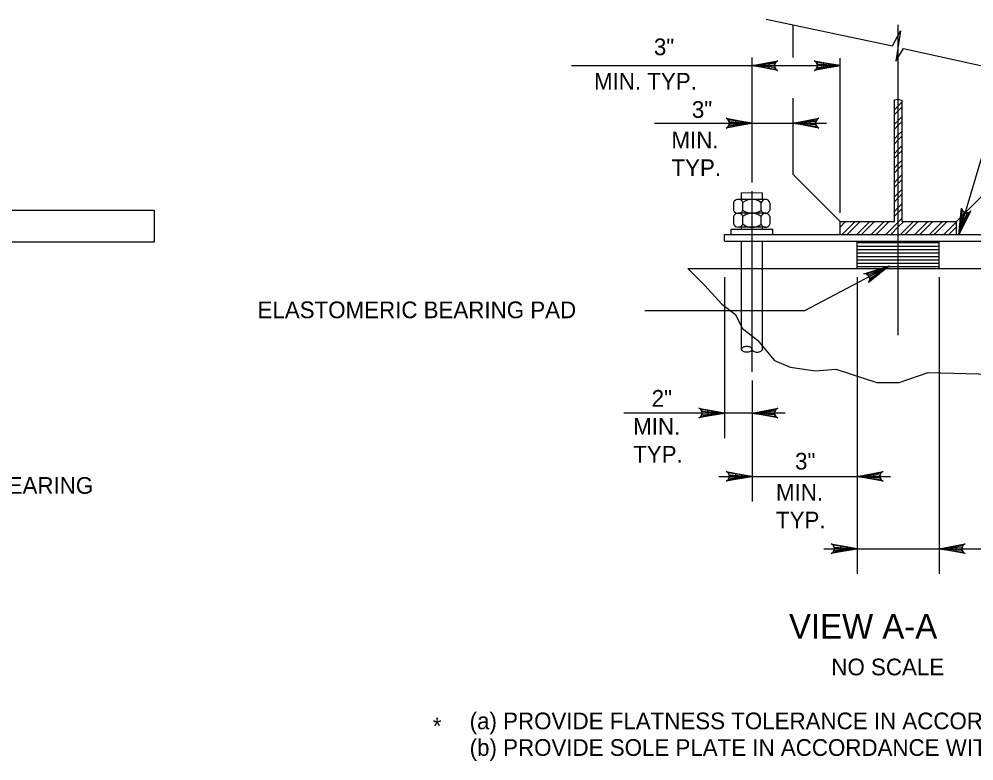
# Model space of a CAD drawing. Extents: x 638175 to 640495, y 294277 to 298435.
# Drawn here: x 639510.9 to 639682.6, y 298033.7 to 298167 of the extents above; entities that cross this region are included whole.
import ezdxf

# ---------------------------------------------------------------- set-up
doc = ezdxf.new("R2010")
doc.units = 0
for name, color, linetype in [('3', 7, 'Continuous'), ('4', 7, 'Continuous'), ('8', 7, 'Continuous')]:
    doc.layers.add(name, color=color, linetype=linetype)

msp = doc.modelspace()

# ---------------------------------------------------------------- linework, layer by layer
at = {"layer": '3'}
for p, q in [((639650.07, 298160.09), (639650.07, 298165.95)), ((639668.98, 298110.18), (639668.98, 298165.93)), ((639650.07, 298139.06), (639650.07, 298152.76)), ((639668.28, 298152.42), (639668.34, 298152.48)), ((639668.28, 298130.61), (639668.28, 298152.47)), ((639668.98, 298151.38), (639669.68, 298152.08)), ((639669.68, 298130.61), (639669.68, 298152.35)), ((639668.28, 298150.68), (639668.98, 298151.38)), ((639668.28, 298149.81), (639668.98, 298150.51)), ((639668.98, 298150.51), (639669.68, 298151.21)), ((639668.28, 298148.07), (639668.98, 298148.77)), ((639668.98, 298148.77), (639669.68, 298149.47)), ((639668.98, 298147.9), (639669.68, 298148.6)), ((639668.28, 298147.2), (639668.98, 298147.9)), ((639668.28, 298145.46), (639668.98, 298146.16)), ((639668.28, 298144.59), (639668.98, 298145.29)), ((639668.98, 298146.16), (639669.68, 298146.86)), ((639668.98, 298145.29), (639669.68, 298145.99)), ((639668.28, 298142.85), (639668.98, 298143.55)), ((639668.98, 298143.55), (639669.68, 298144.25)), ((639668.28, 298141.98), (639668.98, 298142.68)), ((639668.98, 298142.68), (639669.68, 298143.38)), ((639668.28, 298140.24), (639668.98, 298140.94)), ((639668.28, 298139.37), (639668.98, 298140.07)), ((639668.98, 298140.94), (639669.68, 298141.64)), ((639668.98, 298140.07), (639669.68, 298140.77)), ((639668.28, 298137.63), (639668.98, 298138.33)), ((639668.98, 298138.33), (639669.68, 298139.03)), ((639668.28, 298136.76), (639668.98, 298137.46)), ((639668.98, 298137.46), (639669.68, 298138.16)), ((639644.56, 298135.72), (639640.81, 298135.73)), ((639640.81, 298134.57), (639640.81, 298135.73)), ((639642.69, 298103.61), (639642.69, 298136.04)), ((639644.56, 298134.57), (639644.56, 298135.72)), ((639668.28, 298135.02), (639668.98, 298135.72)), ((639668.28, 298134.15), (639668.98, 298134.85)), ((639668.98, 298135.72), (639669.68, 298136.42)), ((639668.98, 298134.85), (639669.68, 298135.55)), ((639639.35, 298134), (639639.35, 298132.66)), ((639645.15, 298134.57), (639640.17, 298134.58)), ((639641.05, 298132.65), (639641.05, 298134)), ((639644.33, 298132.65), (639644.33, 298133.99)), ((639645.91, 298133.98), (639645.91, 298132.64)), ((639668.98, 298133.11), (639669.68, 298133.81)), ((639639.35, 298131.5), (639639.34, 298130.16)), ((639645.15, 298132.07), (639640.17, 298132.08)), ((639641.04, 298130.15), (639641.04, 298131.49)), ((639644.32, 298130.15), (639644.33, 298131.49)), ((639645.91, 298131.48), (639645.91, 298130.14)), ((639668.28, 298132.41), (639668.98, 298133.11)), ((639668.28, 298131.54), (639668.98, 298132.24)), ((639668.98, 298132.24), (639669.68, 298132.94)), ((639658.51, 298128.27), (639658.51, 298130.61)), ((639658.51, 298130.61), (639668.28, 298130.61)), ((639658.51, 298130.47), (639658.65, 298130.61)), ((639658.51, 298129.6), (639659.52, 298130.61)), ((639658.92, 298128.27), (639661.26, 298130.61)), ((639659.79, 298128.27), (639662.13, 298130.61)), ((639661.53, 298128.27), (639663.87, 298130.61)), ((639662.4, 298128.27), (639664.74, 298130.61)), ((639664.14, 298128.27), (639666.48, 298130.61)), ((639665.01, 298128.27), (639667.35, 298130.61)), ((639666.75, 298128.27), (639668.98, 298130.5)), ((639668.98, 298130.5), (639669.68, 298131.2)), ((639668.98, 298129.63), (639669.96, 298130.61)), ((639669.36, 298128.27), (639671.7, 298130.61)), ((639669.68, 298130.61), (639679.45, 298130.61)), ((639670.23, 298128.27), (639672.57, 298130.61)), ((639671.97, 298128.27), (639674.31, 298130.61)), ((639672.84, 298128.27), (639675.18, 298130.61)), ((639674.58, 298128.27), (639676.92, 298130.61)), ((639675.45, 298128.27), (639677.79, 298130.61)), ((639677.19, 298128.27), (639679.45, 298130.53)), ((639679.45, 298128.27), (639679.45, 298130.61)), ((639637.77, 298128.27), (639700.2, 298128.27)), ((639637.77, 298127.09), (639637.77, 298128.27)), ((639638.95, 298129.25), (639646.43, 298129.25)), ((639638.95, 298128.27), (639638.95, 298129.25)), ((639645.14, 298129.57), (639640.16, 298129.58)), ((639640.81, 298129.25), (639640.81, 298129.57)), ((639644.56, 298129.25), (639644.56, 298129.57)), ((639646.43, 298128.27), (639646.43, 298129.25)), ((639667.62, 298128.27), (639668.98, 298129.63)), ((639678.06, 298128.27), (639679.45, 298129.66)), ((639637.77, 298127.09), (639700.2, 298127.09)), ((639640.81, 298122.17), (639640.81, 298127.09)), ((639644.56, 298122.17), (639644.56, 298127.09)), ((639661.6, 298122.17), (639661.6, 298127.09)), ((639661.6, 298127.09), (639661.6, 298127.09)), ((639661.6, 298126.81), (639668.98, 298126.81)), ((639668.98, 298126.81), (639676.36, 298126.81)), ((639676.36, 298122.17), (639676.36, 298127.09)), ((639661.6, 298126.19), (639668.98, 298126.19)), ((639661.6, 298125.57), (639668.98, 298125.57)), ((639661.6, 298124.96), (639668.98, 298124.96)), ((639668.98, 298126.19), (639676.36, 298126.19)), ((639668.98, 298125.57), (639676.36, 298125.57)), ((639668.98, 298124.96), (639676.36, 298124.96)), ((639661.6, 298124.34), (639668.98, 298124.34)), ((639661.6, 298123.73), (639668.98, 298123.73)), ((639661.6, 298123.11), (639668.98, 298123.11)), ((639668.98, 298124.34), (639676.36, 298124.34)), ((639668.98, 298123.73), (639676.36, 298123.73)), ((639668.98, 298123.11), (639676.36, 298123.11)), ((639631.13, 298122.17), (639703.15, 298122.17)), ((639640.81, 298107.62), (639640.81, 298122.17)), ((639644.59, 298122.17), (639644.56, 298122.2)), ((639644.56, 298107.62), (639644.56, 298122.17)), ((639661.6, 298122.5), (639668.98, 298122.5)), ((639668.98, 298122.5), (639676.36, 298122.5))]:
    msp.add_line(p, q, dxfattribs=at)
for points in [[(639668.28, 298152.47), (639668.92, 298152.59), (639669.68, 298152.35)], [(639631.13, 298122.17), (639634.2, 298119.1), (639637.26, 298115.73), (639639.72, 298113.89), (639640.94, 298111.44), (639643.7, 298109.3), (639646.76, 298105.63), (639649.52, 298104.4), (639654.12, 298103.79), (639657.79, 298104.09), (639665.15, 298101.64), (639669.13, 298101.64), (639674.34, 298103.48), (639685.68, 298103.17), (639688.44, 298103.79), (639689.67, 298107.16), (639691.2, 298112.98), (639694.87, 298116.96), (639699.17, 298118.8), (639703.15, 298122.17)]]:
    msp.add_lwpolyline(points, dxfattribs=at)
for centre, radius, start, end in [((639640.2, 298133.67), 0.912, 88.0545, 158.5946), ((639640.2, 298133.67), 0.912, 21.1685, 88.0545), ((639642.69, 298131.96), 2.61, 50.9315, 128.8315), ((639645.12, 298133.74), 0.829, 17.3333, 162.4297), ((639640.2, 298132.99), 0.912, 201.1685, 271.7086), ((639640.19, 298131.16), 0.912, 88.0545, 158.5946), ((639640.2, 298132.99), 0.912, 271.7086, 338.5946), ((639640.19, 298131.16), 0.912, 21.1685, 88.0545), ((639642.68, 298129.46), 2.61, 50.9315, 128.8315), ((639642.69, 298134.68), 2.61, 230.9315, 308.8315), ((639645.12, 298132.89), 0.829, 197.3333, 342.4297), ((639645.12, 298131.24), 0.829, 17.3333, 162.4297), ((639640.19, 298130.49), 0.912, 201.1685, 271.7086), ((639640.19, 298130.49), 0.912, 271.7086, 338.5946), ((639642.69, 298132.18), 2.61, 230.9315, 308.8315), ((639645.11, 298130.39), 0.829, 197.3333, 342.4297), ((639641.09, 298107.64), 0.278, 142.0693, 180), ((639641.09, 298107.64), 0.278, 180, 217.9307), ((639641.41, 298107.4), 0.674, 117.9903, 142.0693), ((639641.41, 298107.89), 0.674, 217.9307, 242.0097), ((639641.61, 298107.01), 1.12, 102.4157, 117.9903), ((639641.75, 298106.39), 1.75, 90, 102.4157), ((639641.75, 298106.39), 1.75, 77.5843, 90), ((639641.89, 298107.01), 1.12, 62.0097, 77.5843), ((639642.1, 298107.4), 0.674, 37.9307, 62.0097), ((639642.1, 298107.89), 0.674, 297.9903, 322.0693), ((639642.41, 298107.64), 0.278, 0, 37.9307), ((639642.41, 298107.64), 0.278, 322.0693, 0), ((639642.96, 298107.62), 0.278, 180, 217.9307), ((639643.28, 298107.87), 0.674, 217.9307, 242.0097), ((639643.97, 298107.87), 0.674, 297.9903, 322.0693), ((639644.28, 298107.62), 0.278, 322.0693, 360), ((639644.28, 298107.62), 0.278, 360, 1.757), ((639641.61, 298108.28), 1.12, 242.0097, 257.5843), ((639641.75, 298108.9), 1.75, 257.5843, 270), ((639641.75, 298108.9), 1.75, 270, 282.4157), ((639641.89, 298108.28), 1.12, 282.4157, 297.9903), ((639643.48, 298108.26), 1.12, 242.0097, 257.5843), ((639643.62, 298108.88), 1.75, 257.5843, 270), ((639643.62, 298108.88), 1.75, 270, 282.4157), ((639643.76, 298108.26), 1.12, 282.4157, 297.9903)]:
    msp.add_arc(centre, radius, start, end, dxfattribs=at)
at = {"layer": '4'}
for p, q in [((639645.23, 298166.98), (639667.92, 298162.15)), ((639667.92, 298162.15), (639669.41, 298164.9)), ((639669.41, 298164.9), (639668.55, 298159.44)), ((639668.55, 298159.44), (639669.92, 298161.71)), ((639669.92, 298161.71), (639695.22, 298156.13)), ((639642.69, 298137.61), (639642.69, 298160.06)), ((639658.51, 298132.17), (639658.51, 298159.94)), ((639610.21, 298158.61), (639658.51, 298158.61)), ((639679.89, 298128.27), (639686.9, 298151.98)), ((639625.17, 298148.28), (639656.07, 298148.28)), ((639493.67, 298132.65), (639535.19, 298132.65)), ((639535.19, 298132.65), (639535.19, 298126.88)), ((639535.19, 298126.88), (639493.67, 298126.88)), ((639667.35, 298122.57), (639652.14, 298114.57)), ((639637.77, 298120.6), (639637.77, 298091.68)), ((639661.6, 298120.6), (639661.6, 298067.29)), ((639676.36, 298120.6), (639676.36, 298067.29)), ((639652.14, 298114.57), (639623.39, 298114.57)), ((639642.69, 298102.04), (639642.69, 298080.28)), ((639648.66, 298096.18), (639619.67, 298096.18)), ((639636.72, 298084.78), (639667.6, 298084.78)), ((639655.63, 298071.79), (639764.22, 298071.79))]:
    msp.add_line(p, q, dxfattribs=at)
for points in [[(639642.69, 298158.61), (639647.35, 298159.48), (639646.99, 298159.23), (639646.8, 298158.92), (639646.75, 298158.61), (639646.8, 298158.3), (639646.99, 298157.98), (639647.35, 298157.73), (639642.69, 298158.61), (639646.99, 298157.98), (639646.8, 298158.3), (639642.69, 298158.61), (639646.75, 298158.61), (639646.8, 298158.92), (639642.69, 298158.61), (639646.99, 298159.23)], [(639658.51, 298158.61), (639653.85, 298157.73), (639654.21, 298157.98), (639654.39, 298158.3), (639654.45, 298158.61), (639654.39, 298158.92), (639654.21, 298159.23), (639653.85, 298159.48), (639658.51, 298158.61), (639654.21, 298159.23), (639654.39, 298158.92), (639658.51, 298158.61), (639654.45, 298158.61), (639654.39, 298158.3), (639658.51, 298158.61), (639654.21, 298157.98)], [(639642.69, 298148.28), (639638.03, 298147.4), (639638.38, 298147.65), (639638.57, 298147.96), (639638.62, 298148.28), (639638.57, 298148.59), (639638.38, 298148.9), (639638.03, 298149.15), (639642.69, 298148.28), (639638.38, 298148.9), (639638.57, 298148.59), (639642.69, 298148.28), (639638.62, 298148.28), (639638.57, 298147.96), (639642.69, 298148.28), (639638.38, 298147.65)], [(639650.07, 298148.28), (639654.73, 298149.15), (639654.37, 298148.9), (639654.19, 298148.59), (639654.13, 298148.28), (639654.19, 298147.96), (639654.37, 298147.65), (639654.73, 298147.4), (639650.07, 298148.28), (639654.37, 298147.65), (639654.19, 298147.96), (639650.07, 298148.28), (639654.13, 298148.28), (639654.19, 298148.59), (639650.07, 298148.28), (639654.37, 298148.9)], [(639679.89, 298128.27), (639680.38, 298132.99), (639680.51, 298132.57), (639680.76, 298132.31), (639681.04, 298132.17), (639681.36, 298132.13), (639681.71, 298132.22), (639682.05, 298132.49), (639679.89, 298128.27), (639681.71, 298132.22), (639681.36, 298132.13), (639679.89, 298128.27), (639681.04, 298132.17), (639680.76, 298132.31), (639679.89, 298128.27), (639680.51, 298132.57)], [(639667.35, 298122.57), (639663.63, 298119.62), (639663.83, 298120.01), (639663.85, 298120.37), (639663.75, 298120.67), (639663.56, 298120.93), (639663.25, 298121.12), (639662.82, 298121.17), (639667.35, 298122.57), (639663.25, 298121.12), (639663.56, 298120.93), (639667.35, 298122.57), (639663.75, 298120.67), (639663.85, 298120.37), (639667.35, 298122.57), (639663.83, 298120.01)], [(639637.77, 298096.18), (639633.11, 298095.31), (639633.46, 298095.56), (639633.65, 298095.87), (639633.7, 298096.18), (639633.65, 298096.49), (639633.46, 298096.81), (639633.11, 298097.06), (639637.77, 298096.18), (639633.46, 298096.81), (639633.65, 298096.49), (639637.77, 298096.18), (639633.7, 298096.18), (639633.65, 298095.87), (639637.77, 298096.18), (639633.46, 298095.56)], [(639642.69, 298096.18), (639647.35, 298097.06), (639646.99, 298096.81), (639646.8, 298096.49), (639646.75, 298096.18), (639646.8, 298095.87), (639646.99, 298095.56), (639647.35, 298095.31), (639642.69, 298096.18), (639646.99, 298095.56), (639646.8, 298095.87), (639642.69, 298096.18), (639646.75, 298096.18), (639646.8, 298096.49), (639642.69, 298096.18), (639646.99, 298096.81)], [(639642.69, 298084.78), (639638.03, 298083.91), (639638.38, 298084.15), (639638.57, 298084.47), (639638.62, 298084.78), (639638.57, 298085.09), (639638.38, 298085.4), (639638.03, 298085.65), (639642.69, 298084.78), (639638.38, 298085.4), (639638.57, 298085.09), (639642.69, 298084.78), (639638.62, 298084.78), (639638.57, 298084.47), (639642.69, 298084.78), (639638.38, 298084.15)], [(639661.6, 298084.78), (639666.26, 298085.65), (639665.9, 298085.4), (639665.72, 298085.09), (639665.66, 298084.78), (639665.72, 298084.47), (639665.9, 298084.15), (639666.26, 298083.91), (639661.6, 298084.78), (639665.9, 298084.15), (639665.72, 298084.47), (639661.6, 298084.78), (639665.66, 298084.78), (639665.72, 298085.09), (639661.6, 298084.78), (639665.9, 298085.4)], [(639661.6, 298071.79), (639656.94, 298070.92), (639657.3, 298071.17), (639657.48, 298071.48), (639657.54, 298071.79), (639657.48, 298072.1), (639657.3, 298072.42), (639656.94, 298072.66), (639661.6, 298071.79), (639657.3, 298072.42), (639657.48, 298072.1), (639661.6, 298071.79), (639657.54, 298071.79), (639657.48, 298071.48), (639661.6, 298071.79), (639657.3, 298071.17)], [(639676.36, 298071.79), (639681.02, 298072.66), (639680.66, 298072.42), (639680.48, 298072.1), (639680.42, 298071.79), (639680.48, 298071.48), (639680.66, 298071.17), (639681.02, 298070.92), (639676.36, 298071.79), (639680.66, 298071.17), (639680.48, 298071.48), (639676.36, 298071.79), (639680.42, 298071.79), (639680.48, 298072.1), (639676.36, 298071.79), (639680.66, 298072.42)]]:
    msp.add_lwpolyline(points, dxfattribs=at)
for points in [[(639645.69, 298159.11), (639645.69, 298158.11), (639642.69, 298158.61)], [(639655.51, 298159.11), (639655.51, 298158.11), (639658.51, 298158.61)], [(639639.69, 298148.78), (639639.69, 298147.78), (639642.69, 298148.28)], [(639653.07, 298148.78), (639653.07, 298147.78), (639650.07, 298148.28)], [(639681.23, 298131.02), (639680.27, 298131.32), (639679.83, 298128.32)], [(639634.77, 298096.68), (639634.77, 298095.68), (639637.77, 298096.18)], [(639645.69, 298096.68), (639645.69, 298095.68), (639642.69, 298096.18)], [(639639.69, 298085.28), (639639.69, 298084.28), (639642.69, 298084.78)], [(639664.6, 298085.28), (639664.6, 298084.28), (639661.6, 298084.78)], [(639658.6, 298072.29), (639658.6, 298071.29), (639661.6, 298071.79)], [(639679.36, 298072.29), (639679.36, 298071.29), (639676.36, 298071.79)]]:
    msp.add_lwpolyline(points, close=True, dxfattribs=at)
msp.add_arc((639642.96, 298107.64), 0.278, 180, 182.0078, dxfattribs=at)
at = {"layer": '8'}
for p, q in [((639658.51, 298130.61), (639650.07, 298139.06)), ((639679.45, 298130.61), (639687.89, 298139.06))]:
    msp.add_line(p, q, dxfattribs=at)

# ---------------------------------------------------------------- texts
at = {"layer": '4'}
for s, height, p in [('3"', 3, (639625.05, 298160.49)), ('MIN. TYP.', 3, (639614.28, 298154.3)), ('3"', 3, (639631.88, 298149.23)), ('MIN.', 3, (639628.2, 298143.77)), ('TYP.', 3, (639628.2, 298138.77)), ('ELASTOMERIC BEARING PAD', 3, (639553.78, 298113.22)), ('2"', 3, (639624.65, 298097.32)), ('MIN.', 3, (639621.32, 298092.27)), ('TYP.', 3, (639621.32, 298087.27)), ('3"', 3, (639650.43, 298086.02)), ('L BEARING', 3, (639502.83, 298081.66)), ('MIN.', 3, (639647, 298080.44)), ('TYP.', 3, (639647, 298075.44)), ('VIEW A-A', 4.429, (639649.34, 298055.64)), ('NO SCALE', 3, (639656.95, 298049.04)), ('(a) PROVIDE FLATNESS TOLERANCE IN ACCORDANCE WITH PUB. 408, SECTION 1105.03(q)', 3, (639591.92, 298039.34)), ('*', 3, (639585.29, 298038.41)), ('(b) PROVIDE SOLE PLATE IN ACCORDANCE WITH DM-4, D14.7.6.3.9dP', 3, (639591.92, 298034.56))]:
    msp.add_text(s, height=height, dxfattribs=at).set_placement(p)

doc.saveas('drawing.dxf')
